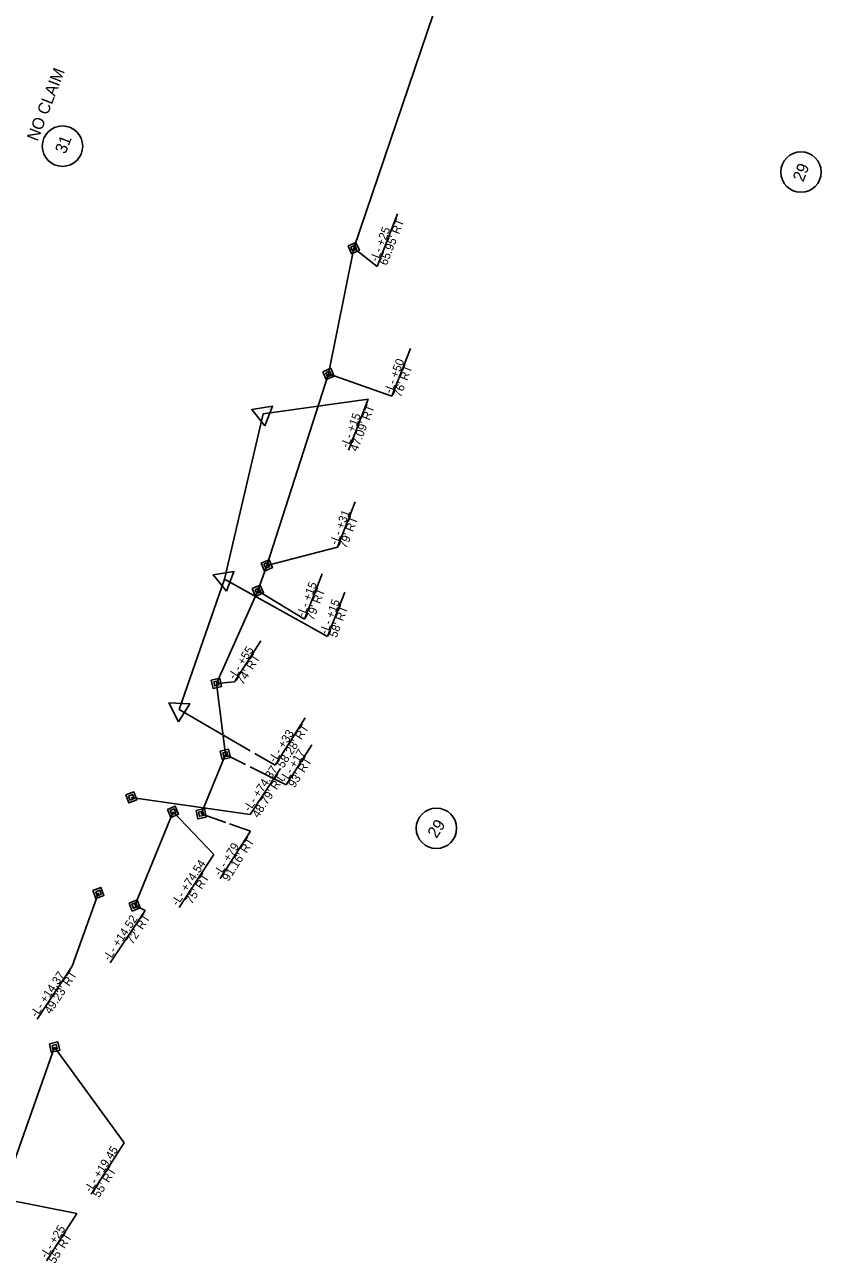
# Model space of a CAD drawing. Extents: x 1975689 to 1978251, y 778490 to 782347.
# Drawn here: x 1977366 to 1977839, y 780574 to 781309 of the extents above; entities that cross this region are included whole.
import ezdxf

# ---------------------------------------------------------------- set-up
doc = ezdxf.new("R2010")
doc.units = 0
for name, color, linetype in [('Prop Easement Permanent Drainage Utility', 7, 'Continuous'), ('Prop Easement Permanent Drainage Utility Station Offsets', 7, 'Continuous'), ('Prop Easement Permanent Utility', 7, 'Continuous'), ('Prop Easement Permanent Utility Station Offsets', 7, 'Continuous'), ('Prop Parcel Number CELL', 7, 'Continuous'), ('Prop ROW Marker CELL', 7, 'Continuous'), ('Prop ROW Permanent Easement CELL', 7, 'Continuous'), ('Prop ROW RW Lines', 7, 'Continuous'), ('Prop ROW Station Offsets', 7, 'Continuous')]:
    doc.layers.add(name, color=color, linetype=linetype)

msp = doc.modelspace()

# ---------------------------------------------------------------- linework, layer by layer
at = {"layer": 'Prop Easement Permanent Drainage Utility'}
msp.add_line((1977431.58, 780786.17), (1977454.32, 780841.8), dxfattribs=at)
at = {"layer": 'Prop Easement Permanent Drainage Utility Station Offsets'}
for p, q in [((1977518.13, 780867.54), (1977500.05, 780840.14)), ((1977500.05, 780840.14), (1977429.54, 780850.33)), ((1977454.32, 780841.8), (1977478.63, 780816.35)), ((1977478.63, 780816.35), (1977457.91, 780784.95)), ((1977410.04, 780793.59), (1977394.5, 780750.18)), ((1977431.58, 780786.17), (1977437.73, 780783.3)), ((1977417.03, 780752.21), (1977437.73, 780783.3)), ((1977373.6, 780718.79), (1977394.5, 780750.18))]:
    msp.add_line(p, q, dxfattribs=at)
at = {"layer": 'Prop Easement Permanent Utility'}
for p, q in [((1977561.58, 781176.39), (1977661.73, 781470.4)), ((1977546.64, 781101.72), (1977561.58, 781176.39)), ((1977509.99, 780988.07), (1977546.64, 781101.72)), ((1977504.69, 780972.98), (1977509.99, 780988.07)), ((1977480.07, 780918.03), (1977504.69, 780972.98)), ((1977485.38, 780875.88), (1977480.07, 780918.03)), ((1977471.05, 780840.64), (1977485.38, 780875.88)), ((1977352.24, 780612.29), (1977384, 780702.12))]:
    msp.add_line(p, q, dxfattribs=at)
at = {"layer": 'Prop Easement Permanent Utility Station Offsets'}
for p, q in [((1977575.59, 781165.51), (1977587.67, 781196.69)), ((1977561.58, 781176.39), (1977575.59, 781165.51)), ((1977584.29, 781088.6), (1977595.24, 781116.87)), ((1977546.64, 781101.72), (1977584.29, 781088.6)), ((1977552.03, 780998.86), (1977562.44, 781025.72)), ((1977509.99, 780988.07), (1977552.03, 780998.86)), ((1977532.44, 780956.15), (1977542.85, 780983)), ((1977504.69, 780972.98), (1977532.44, 780956.15)), ((1977490.9, 780918.92), (1977506.51, 780943.22)), ((1977480.07, 780918.03), (1977490.9, 780918.92)), ((1977485.38, 780875.88), (1977497.25, 780869.95)), ((1977521.54, 780857.81), (1977536.77, 780881.52)), ((1977500.14, 780868.51), (1977521.54, 780857.81)), ((1977471.05, 780840.64), (1977485.58, 780835.47)), ((1977487.88, 780834.65), (1977500.33, 780830.21)), ((1977482.35, 780802.23), (1977500.33, 780830.21)), ((1977384, 780702.12), (1977425.35, 780645.3)), ((1977405.79, 780614.83), (1977425.35, 780645.3)), ((1977397.14, 780603.32), (1977352.24, 780612.29)), ((1977379.16, 780575.34), (1977397.14, 780603.32))]:
    msp.add_line(p, q, dxfattribs=at)
at = {"layer": 'Prop Parcel Number CELL'}
for p, q in [((1977388.7, 781236.92), (1977388.7, 781236.92)), ((1977827.17, 781221.53), (1977827.17, 781221.53)), ((1977610.69, 780831.99), (1977610.69, 780831.99))]:
    msp.add_line(p, q, dxfattribs=at)
for centre in [(1977388.7, 781236.92), (1977827.17, 781221.53), (1977610.69, 780831.99)]:
    msp.add_circle(centre, 12, dxfattribs=at)
at = {"layer": 'Prop ROW Marker CELL'}
for p, q in [((1977561.58, 781176.39), (1977561.58, 781176.39)), ((1977546.64, 781101.72), (1977546.64, 781101.72)), ((1977507.77, 781077.98), (1977507.77, 781077.98)), ((1977509.99, 780988.07), (1977509.99, 780988.07)), ((1977484.88, 780979.94), (1977484.88, 780979.94)), ((1977504.69, 780972.98), (1977504.69, 780972.98)), ((1977480.07, 780918.03), (1977480.07, 780918.03)), ((1977457.94, 780902.49), (1977457.94, 780902.49)), ((1977485.38, 780875.88), (1977485.38, 780875.88)), ((1977429.54, 780850.33), (1977429.54, 780850.33)), ((1977454.32, 780841.8), (1977454.32, 780841.8)), ((1977471.05, 780840.64), (1977471.05, 780840.64)), ((1977410.04, 780793.59), (1977410.04, 780793.59)), ((1977431.58, 780786.17), (1977431.58, 780786.17)), ((1977384, 780702.12), (1977384, 780702.12))]:
    msp.add_line(p, q, dxfattribs=at)
for points in [[(1977508.86, 781070.85), (1977501.05, 781080.58), (1977513.38, 781082.51)], [(1977485.97, 780972.81), (1977478.16, 780982.54), (1977490.49, 780984.47)], [(1977457.57, 780895.29), (1977451.89, 780906.4), (1977464.35, 780905.79)]]:
    msp.add_lwpolyline(points, close=True, dxfattribs=at)
at = {"layer": 'Prop ROW Permanent Easement CELL'}
for points in [[(1977558.22, 781177.69), (1977562.88, 781179.74), (1977564.93, 781175.09), (1977560.27, 781173.03)], [(1977559.9, 781177.04), (1977562.23, 781178.07), (1977563.26, 781175.74), (1977560.93, 781174.71)], [(1977543.28, 781103.02), (1977547.94, 781105.08), (1977549.99, 781100.42), (1977545.33, 781098.36)], [(1977544.96, 781102.37), (1977547.29, 781103.4), (1977548.32, 781101.07), (1977545.99, 781100.04)], [(1977506.64, 780989.37), (1977511.3, 780991.42), (1977513.35, 780986.76), (1977508.69, 780984.71)], [(1977508.32, 780988.72), (1977510.65, 780989.75), (1977511.67, 780987.42), (1977509.34, 780986.39)], [(1977501.33, 780974.28), (1977505.99, 780976.33), (1977508.04, 780971.67), (1977503.38, 780969.62)], [(1977503.01, 780973.63), (1977505.34, 780974.65), (1977506.36, 780972.32), (1977504.04, 780971.3)], [(1977477.04, 780919.98), (1977482.01, 780921.06), (1977483.09, 780916.08), (1977478.12, 780915)], [(1977478.55, 780919), (1977481.04, 780919.54), (1977481.58, 780917.06), (1977479.09, 780916.52)], [(1977482.36, 780877.83), (1977487.33, 780878.91), (1977488.41, 780873.93), (1977483.44, 780872.85)], [(1977483.87, 780876.85), (1977486.36, 780877.39), (1977486.9, 780874.91), (1977484.41, 780874.37)], [(1977426.26, 780851.81), (1977431.02, 780853.61), (1977432.82, 780848.85), (1977428.06, 780847.05)], [(1977427.9, 780851.07), (1977430.28, 780851.97), (1977431.18, 780849.59), (1977428.8, 780848.69)], [(1977450.98, 780843.13), (1977455.66, 780845.14), (1977457.66, 780840.46), (1977452.98, 780838.46)], [(1977452.65, 780842.47), (1977454.99, 780843.47), (1977455.99, 780841.13), (1977453.65, 780840.13)], [(1977468.02, 780842.59), (1977472.99, 780843.67), (1977474.07, 780838.69), (1977469.1, 780837.61)], [(1977469.53, 780841.61), (1977472.02, 780842.16), (1977472.56, 780839.67), (1977470.07, 780839.13)], [(1977406.76, 780795.06), (1977411.52, 780796.87), (1977413.33, 780792.11), (1977408.57, 780790.3)], [(1977408.4, 780794.32), (1977410.78, 780795.23), (1977411.69, 780792.85), (1977409.31, 780791.94)], [(1977428.3, 780787.65), (1977433.06, 780789.45), (1977434.86, 780784.7), (1977430.1, 780782.89)], [(1977429.94, 780786.91), (1977432.32, 780787.81), (1977433.22, 780785.43), (1977430.84, 780784.53)], [(1977380.98, 780704.07), (1977385.95, 780705.15), (1977387.03, 780700.18), (1977382.06, 780699.09)], [(1977382.49, 780703.1), (1977384.98, 780703.64), (1977385.52, 780701.15), (1977383.03, 780700.61)]]:
    msp.add_lwpolyline(points, close=True, dxfattribs=at)
at = {"layer": 'Prop ROW RW Lines'}
for p, q in [((1977484.88, 780979.94), (1977507.77, 781077.98)), ((1977457.94, 780902.49), (1977484.88, 780979.94))]:
    msp.add_line(p, q, dxfattribs=at)
at = {"layer": 'Prop ROW Station Offsets'}
for p, q in [((1977507.77, 781077.98), (1977570.26, 781086.74)), ((1977558.49, 781056.39), (1977570.26, 781086.74)), ((1977484.88, 780979.94), (1977546.1, 780945.83)), ((1977546.1, 780945.83), (1977556.32, 780972.2)), ((1977457.94, 780902.49), (1977500.19, 780878.02)), ((1977514.88, 780869.51), (1977532.85, 780897.49)), ((1977502.98, 780876.4), (1977514.88, 780869.51))]:
    msp.add_line(p, q, dxfattribs=at)

# ---------------------------------------------------------------- texts
at = {"layer": 'Prop Easement Permanent Drainage Utility Station Offsets'}
for s, rotation, p in [('-L- +74.37', 56.5801, (1977499.85, 780841.49)), ("48.79' RT", 56.5801, (1977504.94, 780837.78)), ('-L- +74.54', 56.5801, (1977457.07, 780785.62)), ("75' RT", 56.5801, (1977465.44, 780786.59)), ('-L- +14.52', 56.34162, (1977416.52, 780752.82)), ("72' RT", 56.34162, (1977430.31, 780762.66)), ('-L- +14.37', 56.34162, (1977373.32, 780719.39)), ("49.23' RT", 56.34162, (1977381.6, 780721.31))]:
    msp.add_text(s, height=5, rotation=rotation, dxfattribs=at).set_placement(p)
at = {"layer": 'Prop Easement Permanent Utility Station Offsets'}
for s, rotation, p in [("65.95' RT", 68.82027, (1977581.23, 781165.77)), ('-L- +25', 68.82027, (1977575.73, 781167.89)), ('-L- +50', 68.82027, (1977584.04, 781089.63)), ("76' RT", 68.82027, (1977589.53, 781087.5)), ('-L- +31', 68.82027, (1977551.78, 780999.9)), ("79' RT", 68.82027, (1977557.28, 780997.77)), ('-L- +15', 68.82027, (1977532.19, 780957.18)), ("79' RT", 68.82027, (1977537.69, 780955.05)), ('-L- +55', 57.28837, (1977490.86, 780919.98)), ("74' RT", 57.28837, (1977495.82, 780916.8)), ('-L- +17', 57.28837, (1977521.5, 780858.88)), ("93' RT", 57.28837, (1977526.46, 780855.69)), ('-L- +79', 57.28837, (1977482.31, 780803.29)), ("91.16' RT", 57.28837, (1977487.27, 780800.11)), ('-L- +19.45', 57.28837, (1977405.41, 780615.52)), ("55' RT", 57.28837, (1977410.37, 780612.34)), ('-L- +25', 57.28837, (1977379.13, 780576.4)), ("55' RT", 57.28837, (1977384.08, 780573.22))]:
    msp.add_text(s, height=5, rotation=rotation, dxfattribs=at).set_placement(p)
at = {"layer": 'Prop Parcel Number CELL'}
for s, rotation, p in [('NO CLAIM', 68.74567, (1977373.83, 781239.43)), ('31', 68.74567, (1977390.48, 781231.89)), ('29', 68.74567, (1977828.48, 781215.27)), ('29', 57.28837, (1977610.75, 780825.57))]:
    msp.add_text(s, height=7, rotation=rotation, dxfattribs=at).set_placement(p)
at = {"layer": 'Prop ROW Station Offsets'}
for s, rotation, p in [("47.09' RT", 68.82027, (1977563.74, 781055.29)), ('-L- +15', 68.82027, (1977558.24, 781057.42)), ('-L- +15', 68.82027, (1977545.85, 780946.87)), ("58' RT", 68.82027, (1977551.34, 780944.74)), ('-L- +33', 57.28837, (1977514.84, 780870.57)), ("58.28' RT", 57.28837, (1977519.8, 780867.39))]:
    msp.add_text(s, height=5, rotation=rotation, dxfattribs=at).set_placement(p)

doc.saveas('drawing.dxf')
